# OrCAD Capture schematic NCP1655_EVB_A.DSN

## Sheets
1 02: size A3; title: NCP1655  500W PFC; rev: A
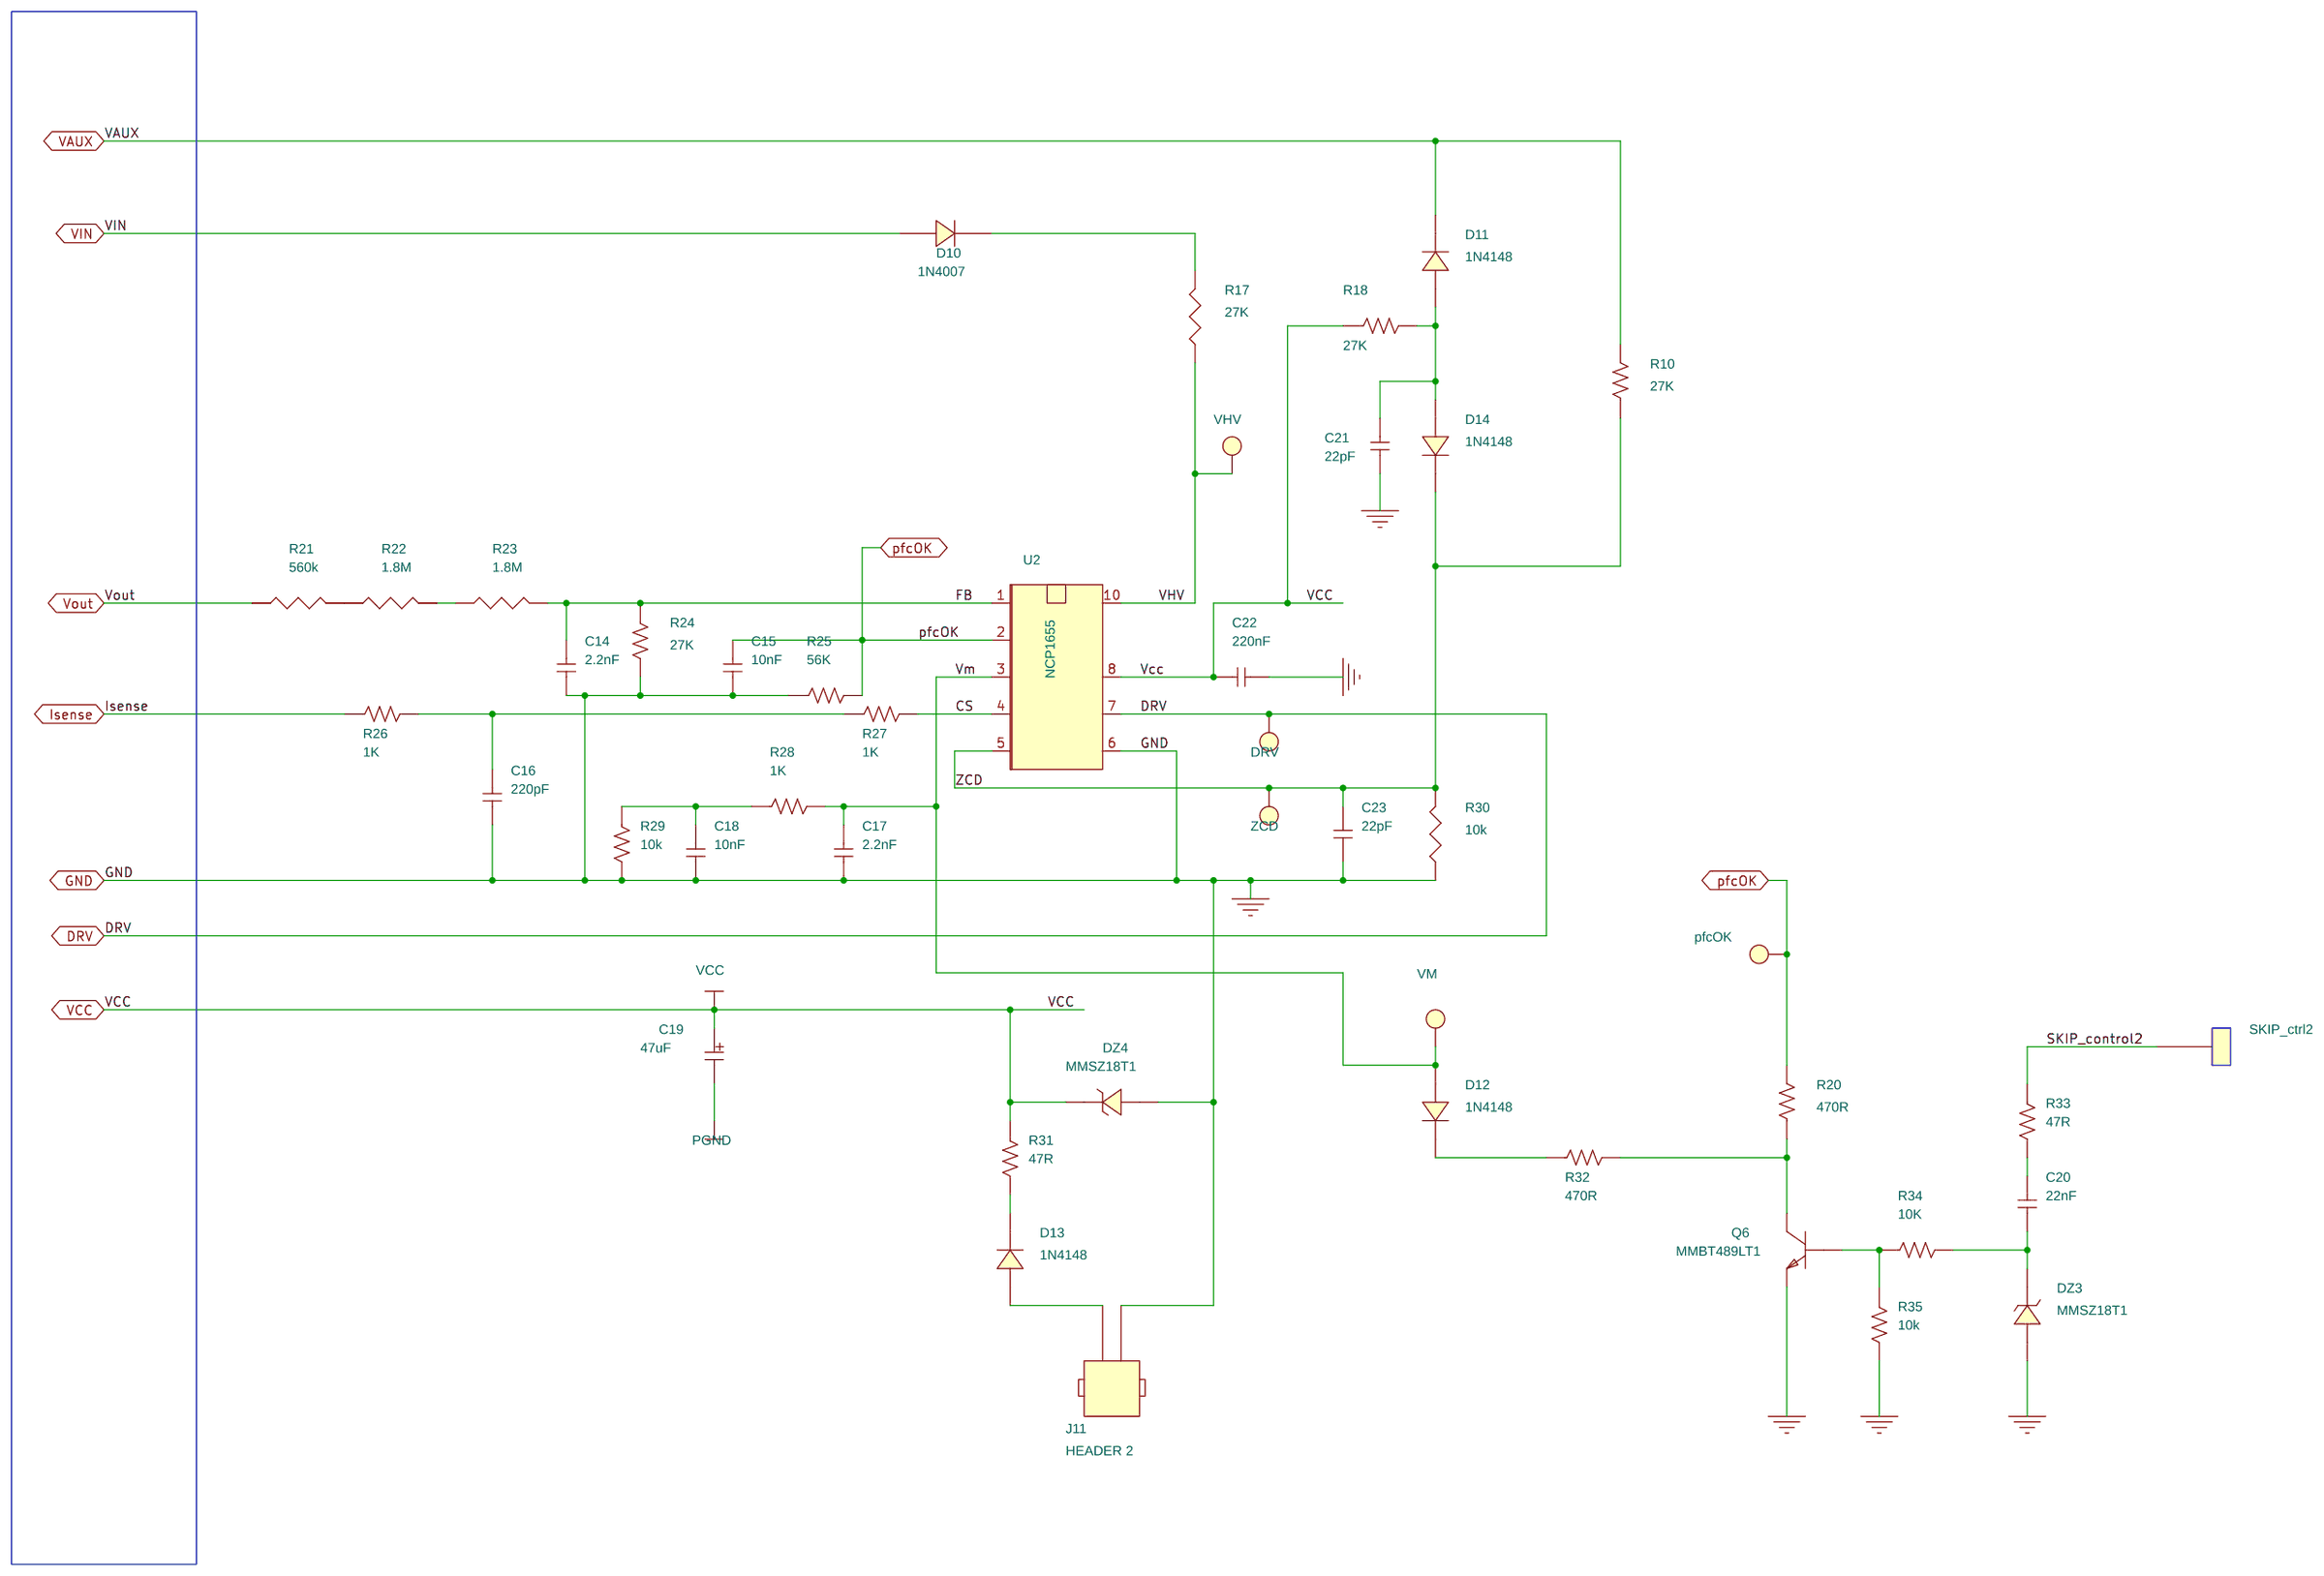
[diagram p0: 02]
2 01: size A3
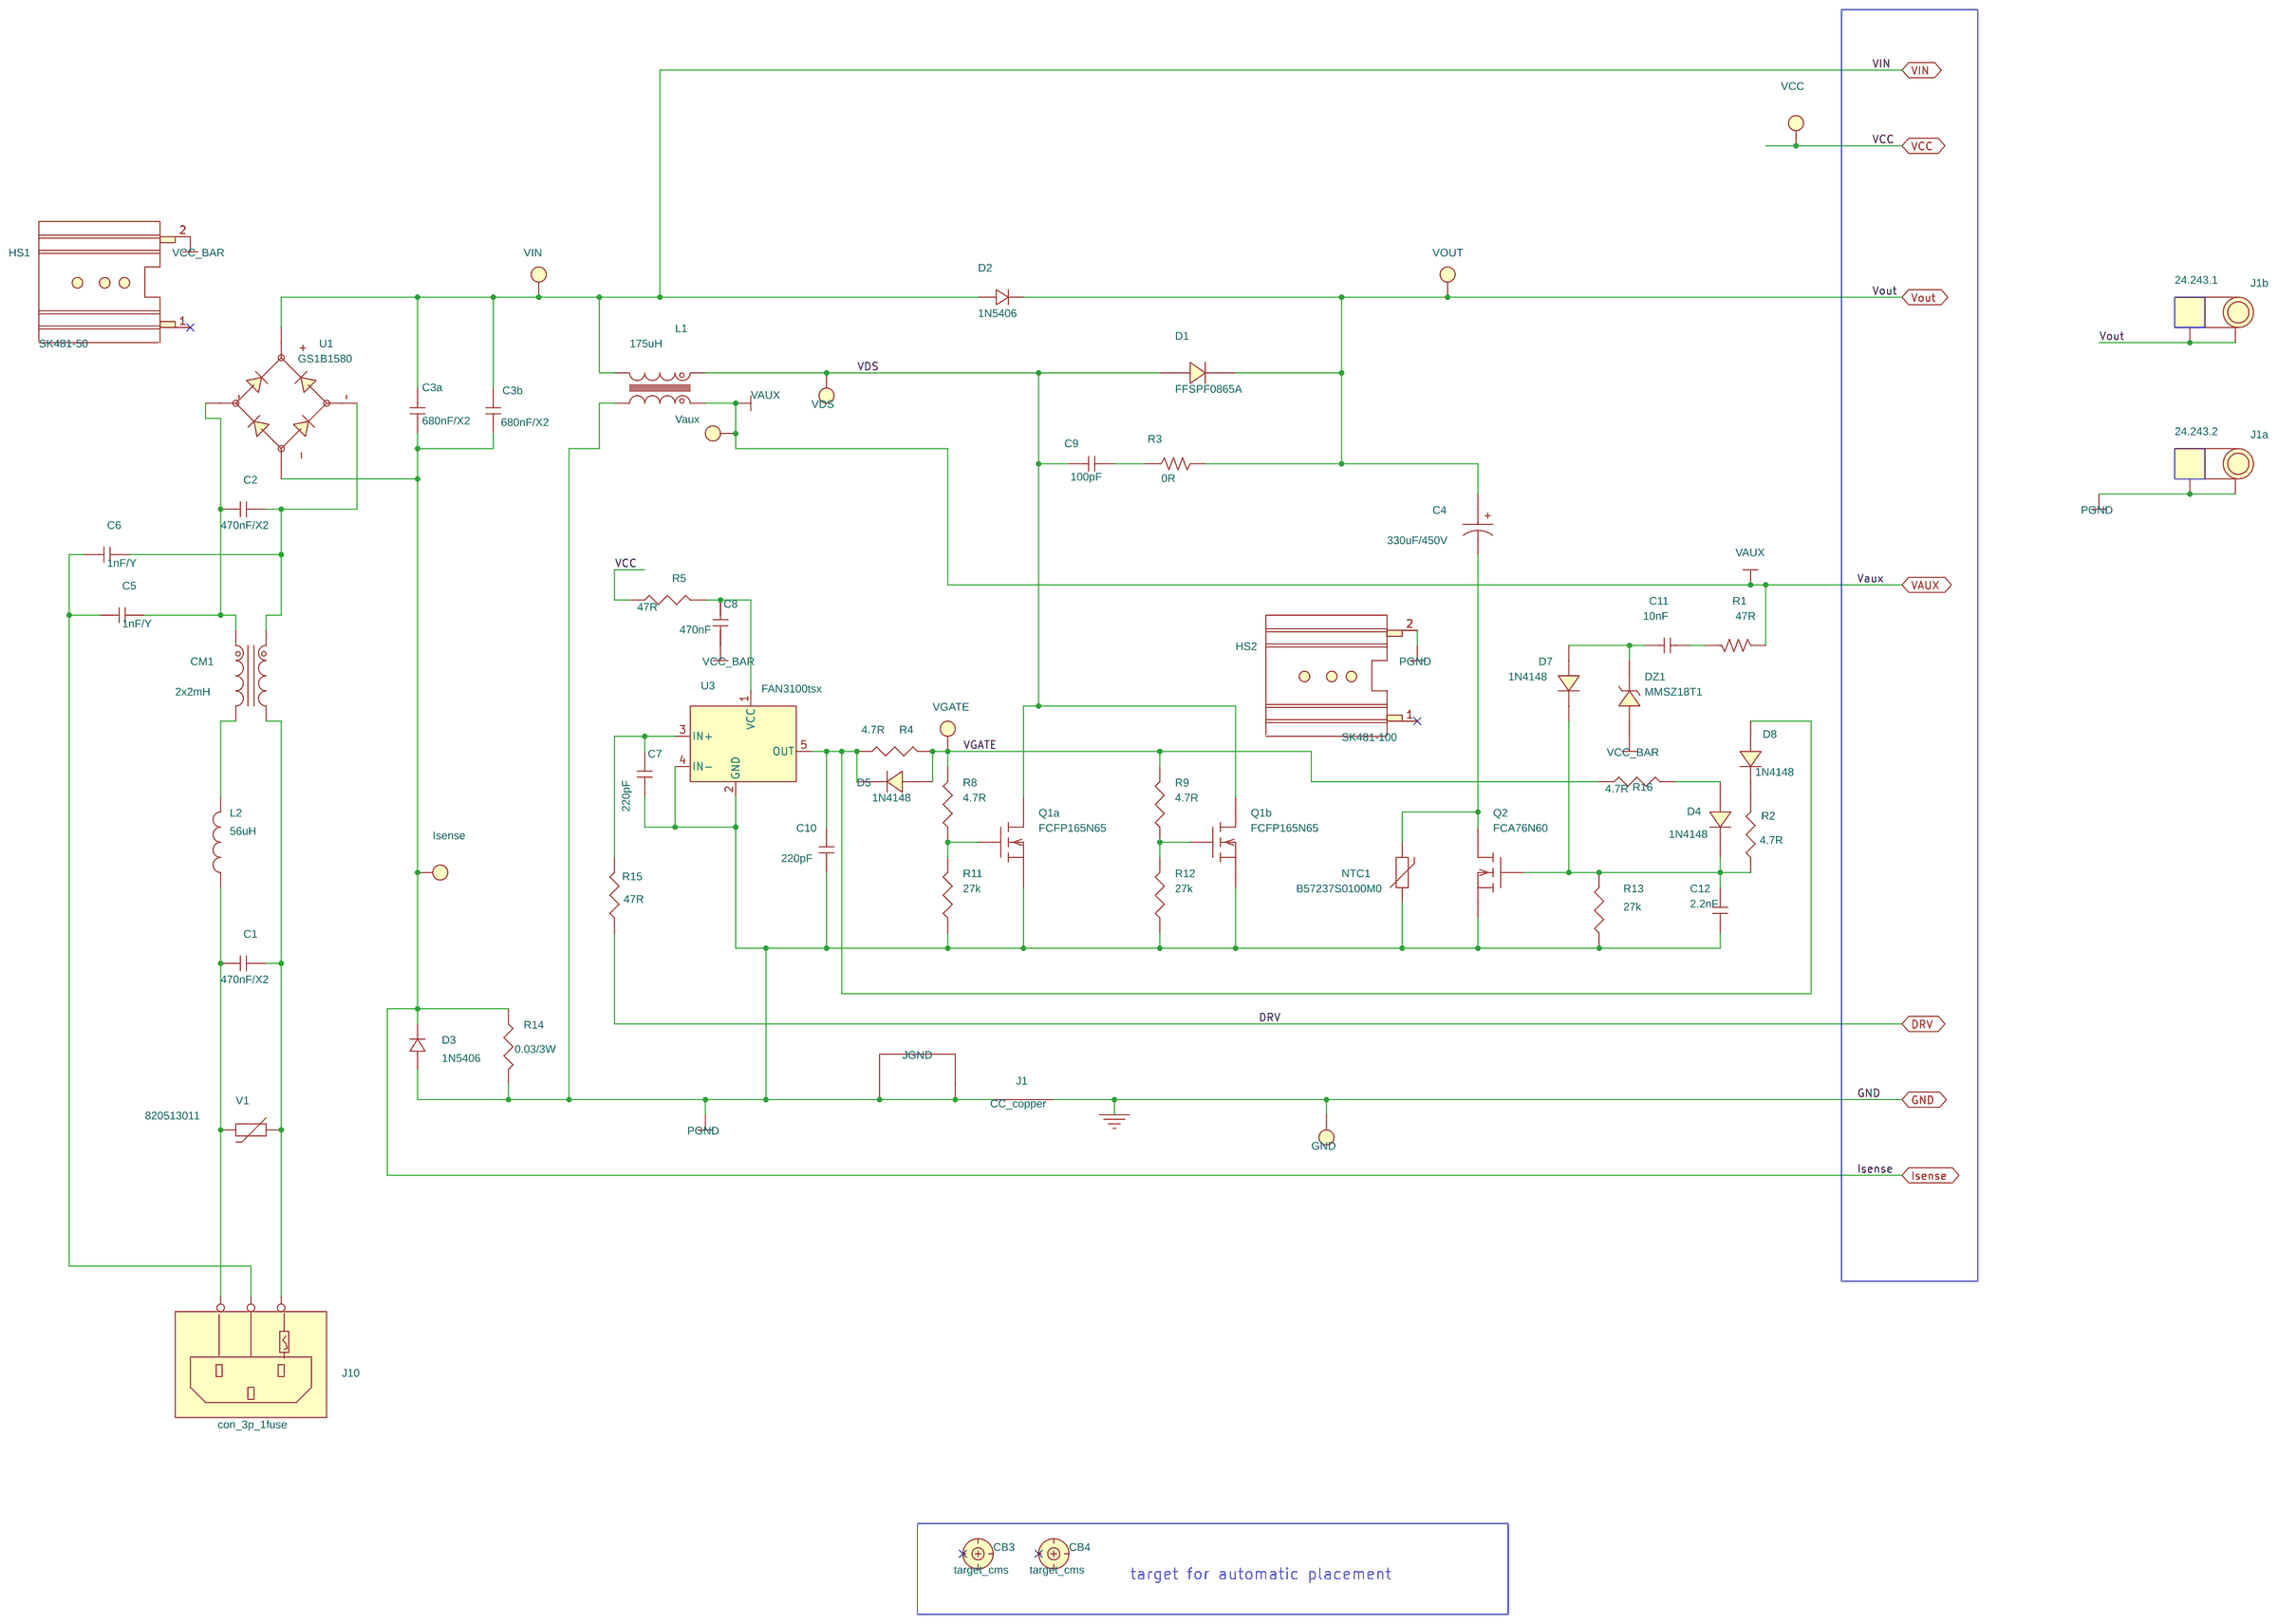
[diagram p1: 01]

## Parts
sheet 01
C1  470nF/X2  [CAP_e9_l18_h17v5_P15_P20]
C2  470nF/X2  [CAP_e9_l18_h17v5_P15_P20]
C3a  680nF/X2  [CAP_e9_l18_h17v5_P15]
C3b  680nF/X2  [CAP_e9_l18_h17v5_P15]
C4  330uF/450V  [CAPA_CH_D35_H42_P10]
C5  1nF/Y  [cap_e4_l13_h9_p10]
C6  1nF/Y  [cap_e4_l13_h9_p10]
C7  220pF  [1206]
C8  470nF  [1206]
C9  100pF  [cap_disk_D5_e3v5_p5]
C10  220pF  [1206]
C11  10nF  [1206]
C12  2.2nF  [1206]
CB3  target_cms  [mire_low]
CB4  target_cms  [mire_low]
CM1  2x2mH  [self_WE-CMB_M]
D1  FFSPF0865A  [TO220_2p]
D2  1N5406  [do201AD]
D3  1N5406  [do201AD]
D4  1N4148  [SOD123]
D5  1N4148  [SOD123]
D7  1N4148  [SOD123]
D8  1N4148  [SOD123]
DZ1  MMSZ18T1  [SOD123]
GND  TP  [TP]
HS1  SK481-50  [disipateur_SK481-50]
HS2  SK481-100  [disipateur_SK481-100]
Isense  TP  [TP]
J1  CC_copper  [none_cust]
J1a  24.243.2  [CONN_BANANE-4MM_H]
J1b  24.243.1  [CONN_BANANE-4MM_H]
J10  con_3p_1fuse  [CON_SCHUTER_GSF1-1201-31]
JGND  STRAP GND  [JUMPER400H]
L1  175uH  [WE_inductor_PWD]
L2  56uH  [self_2310-v-RC]
NTC1  B57237S0100M0  [DISK_D17_E6_P7-5]
Q1a  FCFP165N65  [to220]
Q1b  FCFP165N65  [to220]
Q2  FCA76N60  [TO247]
R1  47R  [1206]
R2  4.7R  [1206]
R3  0R  [res_1w_AC01]
R4  4.7R  [1206]
R5  47R  [1206]
R8  4.7R  [1206]
R9  4.7R  [1206]
R11  27k  [1206]
R12  27k  [1206]
R13  27k  [1206]
R14  0.03/3W  [RES_LVR03]
R15  47R  [1206]
R16  4.7R  [1206]
U1  GS1B1580  [pont_rd_GSI-5S]
U3  FAN3100tsx  [SOT23-5]
V1  820513011  [DISK_D17_E6_P7-5]
Vaux  TP  [TP]
VCC  TP  [TP]
VDS  TP  [TP]
VGATE  TP  [TP]
VIN  TP  [TP]
VOUT  TP  [TP]
sheet 02
C14  2.2nF  [1206]
C15  10nF  [1206]
C16  220pF  [1206]
C17  2.2nF  [1206]
C18  10nF  [1206]
C19  47uF  [CAPA_CH_D5_H11_P2]
C20  22nF  [1206]
C21  22pF  [1206]
C22  220nF  [1206]
C23  22pF  [1206]
D10  1N4007  [DO41]
D11  1N4148  [SOD123]
D12  1N4148  [SOD123]
D13  1N4148  [SOD123]
D14  1N4148  [SOD123]
DRV  TP  [TP]
DZ3  MMSZ18T1  [SOD123]
DZ4  MMSZ18T1  [SOD123]
J11  HEADER 2  [CON_BORNIER_2_P508]
pfcOK  TP  [TP]
Q6  MMBT489LT1  [sot23]
R10  27K  [1206]
R17  27K  [1206]
R18  27K  [1206]
R20  470R  [1206]
R21  560k  [1206]
R22  1.8M  [1206]
R23  1.8M  [1206]
R24  27K  [1206]
R25  56K  [1206]
R26  1K  [1206]
R27  1K  [1206]
R28  1K  [1206]
R29  10k  [1206]
R30  10k  [1206]
R31  47R  [1206]
R32  470R  [1206]
R33  47R  [1206]
R34  10K  [1206]
R35  10k  [1206]
SKIP_ctrl2  TP  [TP_T2]
U2  NCP1655  [SO10_-1_1mm]
VHV  TP  [TP]
VM  TP  [TP]
ZCD  TP  [TP]

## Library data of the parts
C1 C2 C3a C3b C5 C6 C14-C18 C20 C23 = C
C4 = CAP_POL
C7-C10 C12 C21 C22 = C: IC: 18.2V
C11 = C: IC: 25V
CB3 CB4 = target_cms
CM1 = WE-CMB_0: COMPFIXED: NO; COMPGROUP: 0; COMPHEIGHT: 10.000; COMPKEY: NO; COMPLOC: [1112.500,3937.500]; COMPLOCKED: NO; COMPROT: 270; COMPSIDE: TOP; DECOUPLER: NO; MEMORY: NO
D1 D4 D5 D7 D8 D10-D14 = MMSD4148T1_0
D2 D3 = D1N4937_1: COMPFIXED: NO; COMPGROUP: 0; COMPHEIGHT: 0.000; COMPKEY: NO; COMPLOC: [2337.500,1925.000]; COMPLOCKED: NO; COMPROT: 90; COMPSIDE: TOP; DECOUPLER: NO; MEMORY: NO
DZ1 DZ3 DZ4 = zener_sot23_0: MEMORY: NO
DRV GND Isense pfcOK Vaux VCC VDS VGATE VHV VIN VM VOUT ZCD = SLB4-I_90_0: COMPFIXED: NO; COMPGROUP: 0; COMPHEIGHT: 10.000; COMPKEY: NO; COMPLOC: [7512.500,1700.000]; COMPLOCKED: NO; COMPROT: 270; COMPSIDE: TOP; DECOUPLER: NO; MEMORY: NO
HS1 HS2 = Heatsink_KL_196: COMPFIXED: NO; COMPGROUP: 0; COMPHEIGHT: 10.000; COMPKEY: NO; COMPLOC: [5700.000,1875.000]; COMPLOCKED: NO; COMPROT: 270; COMPSIDE: TOP; DECOUPLER: NO; FPLIST: KL195/25.4SW; MEMORY: NO; PART_NUMBER: FR 1319810
J1 = CC_cooper
J1a J1b = HEADER_1_1
J10 = con_3p_1fuse
JGND = STRAP_GND_0
L1 = WE-CMB_1: COMPFIXED: NO; COMPGROUP: 0; COMPHEIGHT: 10.000; COMPKEY: NO; COMPLOC: [1112.500,3937.500]; COMPLOCKED: NO; COMPROT: 270; COMPSIDE: TOP; DECOUPLER: NO; MEMORY: NO
L2 = L_1: COMPFIXED: NO; COMPGROUP: 0; COMPHEIGHT: 10.000; COMPKEY: NO; COMPLOC: [5425.000,3300.000]; COMPLOCKED: NO; COMPROT: 180; COMPSIDE: TOP; DECOUPLER: NO; MEMORY: NO
NTC1 = VARISTOR
Q1a Q1b Q2 = SPP11N60S5
R1 R3 R10 R18 R20 R24-R29 R31-R35 = R_v2
R2 R4 R5 R8 R9 R11-R17 R21-R23 R30 = R
U1 = KBUxK_1: COMPFIXED: NO; COMPGROUP: 0; COMPHEIGHT: 0.000; COMPKEY: NO; COMPLOC: [925.000,287.500]; COMPLOCKED: NO; COMPROT: 0; COMPSIDE: TOP; DECOUPLER: NO; MEMORY: NO; PART_NUMBER: FR_4084799
U3 = FAN3100tsx
V1 = VARISTOR_SYM
C19 = C_elect_0
J11 = HEADER_2
Q6 = MMBT2222AL
SKIP_ctrl2 = TEST_POINT
U2 = NCL3008x_sup_0

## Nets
GND: C14.2 C15.2 C16.2 C17.2 C18.2 C21.2 C22.2 C23.2 DZ3.2(ANODE) DZ4.2(ANODE) GND.1 J1.2 J11.2 Q6.2(EMITTER) R24.2 R25.1 R29.2 R30.1 R35.2 U2.6
PGND: C7.2 C8.2 C10.2 C12.2 C19.2(-) D3.2 DZ1.2(ANODE) HS1.2 HS2.2 J1.1 J1a.1 J1a.2 JGND.1 JGND.2 L1.11 NTC1.1 Q1a.3(s) Q1b.3(s) Q2.3(s) R11.1 R12.1 R13.1 R14.2 U3.2(GND) U3.4(IN-)
VCC: C19.1(+) C22.1 DZ4.1(CATHODE) R5.1 R18.1 R31.1 U2.8 VCC.1
VIN: C3a.2 C3b.2 D2.2 D10.2(A) L1.4 U1.1(+) VIN.1
CS: R27.2 U2.4
DRV: DRV.1 R15.1 U2.7
FB: C14.1 R23.2 R24.1 U2.1
Isense: C3a.1 C3b.1 D3.1 Isense.1 R14.1 R26.1 U1.4(-)
pfcOK: C15.1 pfcOK.1 R20.2 R25.2 U2.2
SKIP_control2: R33.1 SKIP_ctrl2.1
Vaux: D11.1(C) L1.8 R1.2 R10.2 Vaux.1
VDS: C9.2 D1.2(A) L1.3 Q1a.2(d) Q1b.2(d) VDS.1
VGATE: D5.2(A) R4.2 R8.2 R9.2 R16.1 VGATE.1
VHV: R17.1 U2.10 VHV.1
Vm: C17.1 D12.2(A) R28.2 U2.3 VM.1
Vout: C4.1 D1.1(C) D2.1 J1b.1 J1b.2 R3.2 R21.1 VOUT.1
ZCD: C23.1 D14.1(C) R10.1 R30.2 U2.5 ZCD.1
N12553072: C1.1 J10.3 L2.1 V1.2
N12553076: C1.2 CM1.2 J10.1 V1.1
N12553080: C5.1 C6.1 J10.2
N12553128: CM1.3 L2.2
N12553139: C2.2 C6.2 CM1.1 U1.3(ac2)
N12553193: C2.1 C5.2 CM1.4 U1.2(ac1)
N12561389: C11.1 R1.1
N12563930: C7.1 R15.2 U3.3(IN+)
N12564274: Q1a.1(g) R8.1 R11.2
N12565260: Q1b.1(g) R9.1 R12.2
N12565625: C4.2 NTC1.2 Q2.2(d)
N12565696: C12.1 D4.1(C) D7.1(C) Q2.1(g) R2.1 R13.2
N12566266: C9.1 R3.1
N12573614: D10.1(C) R17.2
N12574373: R22.2 R23.1
N12574975: C16.1 R26.2 R27.1
N12575513: C18.1 R28.1 R29.1
N12576392: C21.1 D11.2(A) D14.2(A) R18.2
N12577351: D13.1(C) R31.2
N12577403: D13.2(A) J11.1
N12578828: C20.1 R33.2
N12578907: C20.2 DZ3.1(CATHODE) R34.2
N12579145: Q6.1(BASE) R34.1 R35.1
N12580736: D12.1(C) R32.1
N12597521: D4.2(A) R16.2
N12608976: Q6.3(COLLECTOR) R20.1 R32.2
N12612062: R21.2 R22.1
N12614639: C11.2 D7.2(A) DZ1.1(CATHODE)
N12616473: C10.1 D5.1(C) D8.2(A) R4.1 U3.5(OUT)
N12617768: C8.1 R5.2 U3.1(VCC)
N12619697: D8.1(C) R2.2

Not connected (* = marked no-connect by the designer): CB3 1*; CB4 1*; HS1 1*; HS2 1*

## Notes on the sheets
sheet 2
- target for automatic placement
